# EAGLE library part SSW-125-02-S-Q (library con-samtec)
THROUGH-HOLE .025" SQ POST SOCKET Source: Samtec SSW.pdf
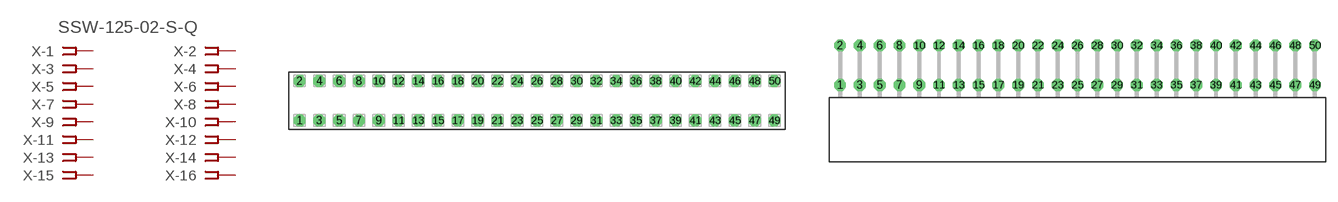
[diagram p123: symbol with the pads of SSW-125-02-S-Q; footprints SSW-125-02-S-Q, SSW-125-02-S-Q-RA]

Designator prefix X; gates -1=FPINV -2=FPIN -3=FPIN -4=FPIN -5=FPIN -6=FPIN -7=FPIN -8=FPIN -9=FPIN -10=FPIN -11=FPIN -12=FPIN -13=FPIN -14=FPIN -15=FPIN -16=FPIN -17=FPIN -18=FPIN -19=FPIN -20=FPIN -21=FPIN -22=FPIN -23=FPIN -24=FPIN -25=FPIN -26=FPIN -27=FPIN -28=FPIN -29=FPIN -30=FPIN -31=FPIN -32=FPIN -33=FPIN -34=FPIN -35=FPIN -36=FPIN -37=FPIN -38=FPIN -39=FPIN -40=FPIN -41=FPIN -42=FPIN -43=FPIN -44=FPIN -45=FPIN -46=FPIN -47=FPIN -48=FPIN -49=FPIN -50=FPIN

## SSW-125-02-S-Q (MPN: SSW-125-02-S-Q; OC_FARNELL: unknown; OC_NEWARK: 82P9297)  [SSW-125-02-S-Q]
1  -1:1  pas
2  -2:1  pas
3  -3:1  pas
4  -4:1  pas
5  -5:1  pas
6  -6:1  pas
7  -7:1  pas
8  -8:1  pas
9  -9:1  pas
10  -10:1  pas
11  -11:1  pas
12  -12:1  pas
13  -13:1  pas
14  -14:1  pas
15  -15:1  pas
16  -16:1  pas
17  -17:1  pas
18  -18:1  pas
19  -19:1  pas
20  -20:1  pas
21  -21:1  pas
22  -22:1  pas
23  -23:1  pas
24  -24:1  pas
25  -25:1  pas
26  -26:1  pas
27  -27:1  pas
28  -28:1  pas
29  -29:1  pas
30  -30:1  pas
31  -31:1  pas
32  -32:1  pas
33  -33:1  pas
34  -34:1  pas
35  -35:1  pas
36  -36:1  pas
37  -37:1  pas
38  -38:1  pas
39  -39:1  pas
40  -40:1  pas
41  -41:1  pas
42  -42:1  pas
43  -43:1  pas
44  -44:1  pas
45  -45:1  pas
46  -46:1  pas
47  -47:1  pas
48  -48:1  pas
49  -49:1  pas
50  -50:1  pas

## SSW-125-02-S-QRA (MPN: SSW-125-02-S-Q-RA; OC_FARNELL: unknown; OC_NEWARK: 82P9298)  [SSW-125-02-S-Q-RA]
Pads as for SSW-125-02-S-Q

## Footprint SSW-125-02-S-Q (pad centres in mm)
THROUGH-HOLE .025" SQ POST SOCKET Source: Samtec SSW.pdf
drill 1 pad 1.5 octagon: 1 -30.48,-2.54; 2 -30.48,2.54; 3 -27.94,-2.54; 4 -27.94,2.54; 5 -25.4,-2.54; 6 -25.4,2.54; 7 -22.86,-2.54; 8 -22.86,2.54; 9 -20.32,-2.54; 10 -20.32,2.54; 11 -17.78,-2.54; 12 -17.78,2.54; 13 -15.24,-2.54; 14 -15.24,2.54; 15 -12.7,-2.54; 16 -12.7,2.54; 17 -10.16,-2.54; 18 -10.16,2.54; 19 -7.62,-2.54; 20 -7.62,2.54; 21 -5.08,-2.54; 22 -5.08,2.54; 23 -2.54,-2.54; 24 -2.54,2.54; 25 0,-2.54; 26 0,2.54; 27 2.54,-2.54; 28 2.54,2.54; 29 5.08,-2.54; 30 5.08,2.54; 31 7.62,-2.54; 32 7.62,2.54; 33 10.16,-2.54; 34 10.16,2.54; 35 12.7,-2.54; 36 12.7,2.54; 37 15.24,-2.54; 38 15.24,2.54; 39 17.78,-2.54; 40 17.78,2.54; 41 20.32,-2.54; 42 20.32,2.54; 43 22.86,-2.54; 44 22.86,2.54; 45 25.4,-2.54; 46 25.4,2.54; 47 27.94,-2.54; 48 27.94,2.54; 49 30.48,-2.54; 50 30.48,2.54

## Footprint SSW-125-02-S-Q-RA (pad centres in mm)
THROUGH-HOLE .025" SQ POST SOCKET Source: Samtec SSW.pdf
drill 1 pad 1.5 octagon: 1 -30.48,1.524; 2 -30.48,6.604; 3 -27.94,1.524; 4 -27.94,6.604; 5 -25.4,1.524; 6 -25.4,6.604; 7 -22.86,1.524; 8 -22.86,6.604; 9 -20.32,1.524; 10 -20.32,6.604; 11 -17.78,1.524; 12 -17.78,6.604; 13 -15.24,1.524; 14 -15.24,6.604; 15 -12.7,1.524; 16 -12.7,6.604; 17 -10.16,1.524; 18 -10.16,6.604; 19 -7.62,1.524; 20 -7.62,6.604; 21 -5.08,1.524; 22 -5.08,6.604; 23 -2.54,1.524; 24 -2.54,6.604; 25 0,1.524; 26 0,6.604; 27 2.54,1.524; 28 2.54,6.604; 29 5.08,1.524; 30 5.08,6.604; 31 7.62,1.524; 32 7.62,6.604; 33 10.16,1.524; 34 10.16,6.604; 35 12.7,1.524; 36 12.7,6.604; 37 15.24,1.524; 38 15.24,6.604; 39 17.78,1.524; 40 17.78,6.604; 41 20.32,1.524; 42 20.32,6.604; 43 22.86,1.524; 44 22.86,6.604; 45 25.4,1.524; 46 25.4,6.604; 47 27.94,1.524; 48 27.94,6.604; 49 30.48,1.524; 50 30.48,6.604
